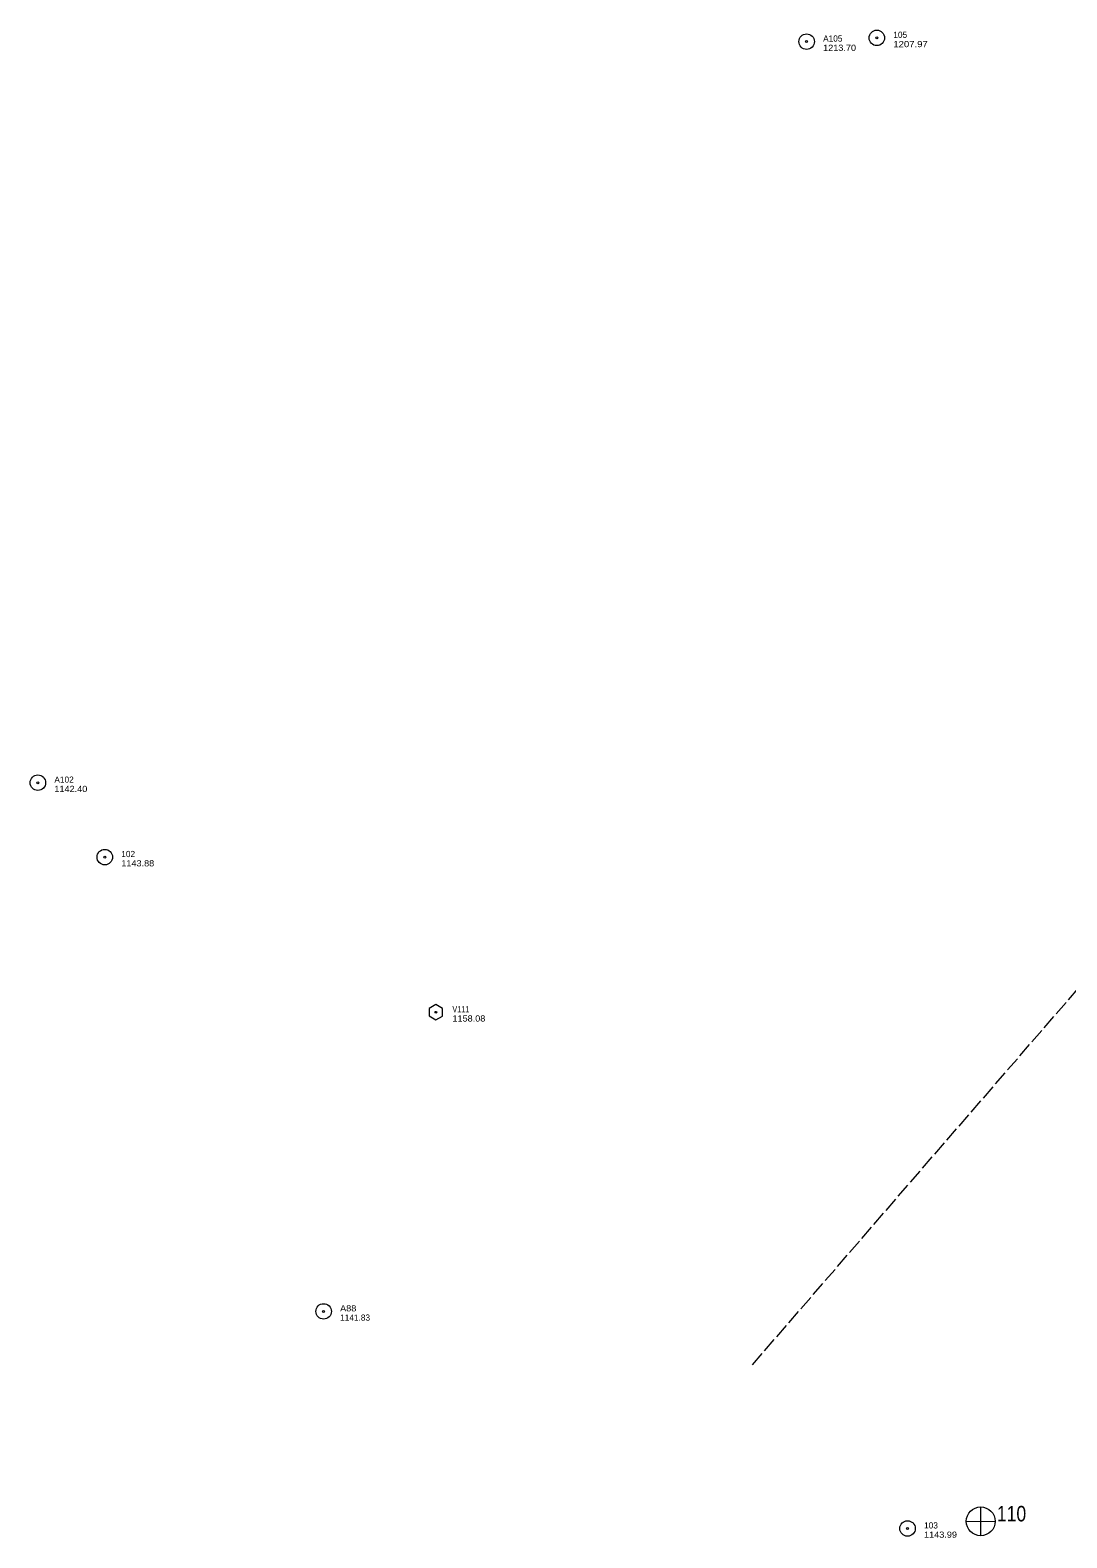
# Model space of a CAD drawing. Extents: x 297327 to 299792, y 46897 to 49095.
# Drawn here: x 297327 to 298332, y 47634 to 49095 of the extents above; entities that cross this region are included whole.
import ezdxf

# ---------------------------------------------------------------- set-up
doc = ezdxf.new("R2010")
doc.units = 0
doc.header["$LTSCALE"] = 2.4
doc.linetypes.add('LONG_DASHED', pattern=[7.5, 6, -1.5])
for name, color, linetype, lineweight in [('4', 7, 'Continuous', 13), ('5', 7, 'Continuous', 13), ('6', 7, 'Continuous', 13)]:
    doc.layers.add(name, color=color, linetype=linetype, lineweight=lineweight)

msp = doc.modelspace()

# ---------------------------------------------------------------- linework, layer by layer
at = {"layer": '4', "linetype": 'LONG_DASHED'}
msp.add_line((298026.893, 47801.312), (298725.651, 48608.445), dxfattribs=at)
at = {"layer": '4'}
for p, q in [((298248.127, 47663.739), (298248.062, 47635.885)), ((298234.218, 47649.709), (298262.123, 47649.696))]:
    msp.add_line(p, q, dxfattribs=at)
msp.add_circle((298248.179, 47649.717), 14, dxfattribs=at)
at = {"layer": '5'}
msp.add_lwpolyline([(297713.805, 48146.728), (297713.805, 48139.337), (297720.265, 48135.61), (297726.662, 48139.275), (297726.662, 48146.604), (297720.14, 48150.33)], close=True, dxfattribs=at)
msp.add_circle((297720.219, 48142.965), 0.871, dxfattribs=at)
at = {"layer": '6'}
for centre, radius in [((298079.469, 49083.439), 7.5), ((298079.469, 49083.439), 0.96), ((298147.531, 49087.033), 7.5), ((298147.531, 49087.033), 0.96), ((297334.491, 48365.351), 7.5), ((297334.491, 48365.351), 0.96), ((297399.32, 48293.297), 7.5), ((297399.32, 48293.297), 0.96), ((297611.395, 47853.106), 7.5), ((297611.395, 47853.106), 0.96), ((298177.3, 47642.792), 7.5), ((298177.3, 47642.792), 0.96)]:
    msp.add_circle(centre, radius, dxfattribs=at)

# ---------------------------------------------------------------- texts
at = {"layer": '4', "width": 0.85}
msp.add_text('110', height=15, dxfattribs=at).set_placement((298263.831, 47649.647))
at = {"layer": '5'}
for s, width, p in [('V111', 0.8, (297736.219, 48142.965)), ('1158.08', 1.1, (297736.219, 48133.965))]:
    msp.add_text(s, height=6, dxfattribs=dict(at, width=width)).set_placement(p)
at = {"layer": '6'}
for s, p in [('A105', (298095.469, 49083.439)), ('105', (298163.531, 49087.033)), ('A102', (297350.491, 48365.351)), ('102', (297415.32, 48293.297)), ('1141.83', (297627.395, 47844.106)), ('103', (298193.3, 47642.792))]:
    msp.add_text(s, height=6, dxfattribs=at).set_placement(p)
for s, width, p in [('1207.97', 1.15, (298163.531, 49078.033)), ('1213.70', 1.1, (298095.469, 49074.439)), ('1142.40', 1.1, (297350.491, 48356.351)), ('1143.88', 1.1, (297415.32, 48284.297)), ('A88', 1.1, (297627.395, 47853.106)), ('1143.99', 1.1, (298193.3, 47633.792))]:
    msp.add_text(s, height=6, dxfattribs=dict(at, width=width)).set_placement(p)

doc.saveas('drawing.dxf')
